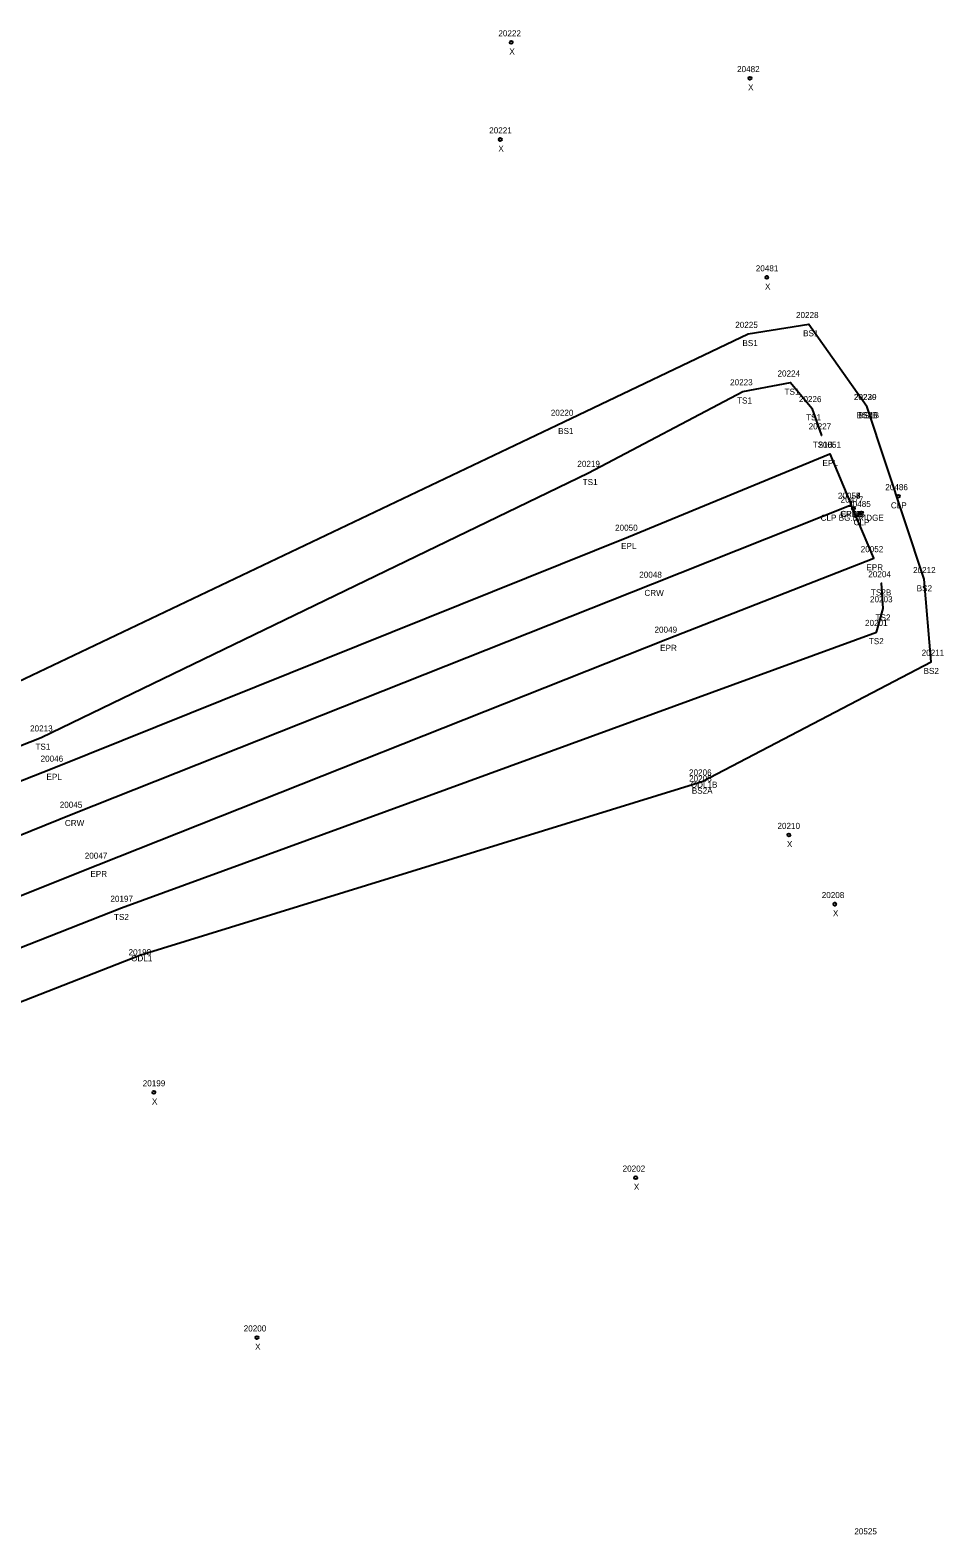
# Model space of a CAD drawing. Extents: x 1966740 to 1969291, y 1117378 to 1118461.
# Drawn here: x 1967562.8 to 1967713.2, y 1117652.7 to 1117901 of the extents above; entities that cross this region are included whole.
import ezdxf

# ---------------------------------------------------------------- set-up
doc = ezdxf.new("R2010")
doc.units = 0
for name, color, linetype in [('RD_DTM_BkLn1', 7, 'Continuous'), ('RD_DTM_BkLn2', 7, 'Continuous'), ('RD_EX_H2O', 7, 'Continuous'), ('RD_EX_H2O_txCode', 7, 'Continuous'), ('RD_EX_Road', 7, 'Continuous'), ('RD_EX_Road_txCode', 7, 'Continuous'), ('RD_SMD_Locator', 7, 'Continuous'), ('RD_SMD_Misc', 7, 'Continuous')]:
    doc.layers.add(name, color=color, linetype=linetype)

msp = doc.modelspace()

# ---------------------------------------------------------------- linework, layer by layer
at = {"layer": 'RD_DTM_BkLn1'}
msp.add_lwpolyline([(1966772.57, 1117449.88), (1966874.49, 1117489.87), (1966974.64, 1117529.93), (1967075.06, 1117571.68), (1967175.91, 1117613.34), (1967274.11, 1117653.69), (1967325.25, 1117674.8), (1967374.73, 1117695), (1967473.9, 1117733.1), (1967569.8, 1117771.9), (1967665.19, 1117809.79), (1967697.89, 1117822.8)], dxfattribs=at)
at = {"layer": 'RD_DTM_BkLn2'}
for points in [[(1967560.73, 1117793.63), (1967650.63, 1117836.46), (1967680.95, 1117850.94), (1967690.95, 1117852.56), (1967700.5, 1117839.06)], [(1966768.15, 1117461.43), (1966869.41, 1117499.34), (1967070.52, 1117582.35), (1967171.25, 1117624.02), (1967269.74, 1117664.9), (1967320.21, 1117685.71), (1967369.37, 1117708.48), (1967468.51, 1117746.66), (1967564.6, 1117784.47), (1967654.68, 1117828.05), (1967680.1, 1117841.48), (1967687.91, 1117842.93), (1967691.45, 1117838.71), (1967693.03, 1117834.22)], [(1967673.4, 1117777.22), (1967711.06, 1117796.94), (1967709.93, 1117810.55), (1967700.5, 1117839.06)], [(1967334.06, 1117655.75), (1967334.81, 1117659.44), (1967379.1, 1117675.46), (1967480.83, 1117718.27), (1967577.81, 1117756.42), (1967702.07, 1117801.85), (1967703.17, 1117805.75), (1967702.89, 1117809.87)]]:
    msp.add_lwpolyline(points, dxfattribs=at)
at = {"layer": 'RD_EX_H2O'}
msp.add_lwpolyline([(1967336.04, 1117656.91), (1967380.56, 1117671.84), (1967483.89, 1117710.7), (1967580.8, 1117748.62), (1967673.4, 1117777.22)], dxfattribs=at)
at = {"layer": 'RD_EX_Road'}
for points in [[(1966769.51, 1117457.48), (1966870.16, 1117497.34), (1966971.19, 1117538.95), (1967071.09, 1117580.24), (1967172.6, 1117621.53), (1967270.79, 1117661.66), (1967321.12, 1117682.57), (1967371.52, 1117702.88), (1967470.26, 1117741.55), (1967566.67, 1117779.5), (1967661.25, 1117817.53), (1967694.4, 1117831.19), (1967697.89, 1117822.8)], [(1967340.03, 1117669.86), (1967379.26, 1117686.2), (1967476.09, 1117724.39), (1967573.92, 1117763.51), (1967667.7, 1117800.74), (1967701.64, 1117814), (1967697.89, 1117822.8)]]:
    msp.add_lwpolyline(points, dxfattribs=at)
at = {"layer": 'RD_SMD_Locator'}
for centre, radius in [((1967641.96, 1117898.96), 0.25), ((1967681.25, 1117893.06), 0.25), ((1967640.16, 1117882.97), 0.25), ((1967684.04, 1117860.25), 0.25), ((1967680.95, 1117850.94), 0.001), ((1967690.95, 1117852.56), 0.001), ((1967680.1, 1117841.48), 0.001), ((1967687.91, 1117842.93), 0.001), ((1967691.45, 1117838.71), 0.001), ((1967700.5, 1117839.06), 0.001), ((1967700.5, 1117839.06), 0.001), ((1967650.63, 1117836.46), 0.001), ((1967693.03, 1117834.22), 0.001), ((1967694.4, 1117831.19), 0.001), ((1967654.68, 1117828.05), 0.001), ((1967705.67, 1117824.21), 0.25), ((1967697.89, 1117822.8), 0.001), ((1967697.89, 1117822.8), 0.001), ((1967697.89, 1117822.8), 0.001), ((1967698.29, 1117822.17), 0.25), ((1967699.54, 1117821.44), 0.25), ((1967661.25, 1117817.53), 0.001), ((1967701.64, 1117814), 0.001), ((1967665.19, 1117809.79), 0.001), ((1967702.89, 1117809.87), 0.001), ((1967709.93, 1117810.55), 0.001), ((1967703.17, 1117805.75), 0.001), ((1967702.07, 1117801.85), 0.001), ((1967667.7, 1117800.74), 0.001), ((1967711.06, 1117796.94), 0.001), ((1967564.6, 1117784.47), 0.001), ((1967566.67, 1117779.5), 0.001), ((1967673.4, 1117777.22), 0.001), ((1967673.4, 1117777.22), 0.001), ((1967569.8, 1117771.9), 0.001), ((1967687.66, 1117768.42), 0.25), ((1967573.92, 1117763.51), 0.001), ((1967695.23, 1117757.03), 0.25), ((1967577.81, 1117756.42), 0.001), ((1967580.8, 1117748.62), 0.001), ((1967583.14, 1117726.03), 0.25), ((1967662.45, 1117711.98), 0.25), ((1967600.11, 1117685.65), 0.25)]:
    msp.add_circle(centre, radius, dxfattribs=at)

# ---------------------------------------------------------------- texts
at = {"layer": 'RD_EX_H2O_txCode'}
for s, p in [('20205', (1967671.24, 1117777.22)), ('ODL1B', (1967671.51, 1117776.22)), ('20198', (1967578.97, 1117748.62)), ('ODL1', (1967579.39, 1117747.62))]:
    msp.add_text(s, height=1, dxfattribs=at).set_placement(p)
at = {"layer": 'RD_EX_Road_txCode'}
for s, p in [('20051', (1967692.52, 1117832.19)), ('EPL', (1967693.19, 1117829.19)), ('20054', (1967695.73, 1117823.8)), ('20055', (1967695.73, 1117823.8)), ('EPRB', (1967696.19, 1117820.8)), ('EPLB', (1967696.22, 1117820.8)), ('20050', (1967659.05, 1117818.53)), ('EPL', (1967660.04, 1117815.53)), ('20052', (1967699.48, 1117815)), ('EPR', (1967700.41, 1117812)), ('20049', (1967665.54, 1117801.74)), ('EPR', (1967666.47, 1117798.74)), ('20046', (1967564.49, 1117780.5)), ('EPL', (1967565.46, 1117777.5)), ('20047', (1967571.76, 1117764.51)), ('EPR', (1967572.69, 1117761.51))]:
    msp.add_text(s, height=1, dxfattribs=at).set_placement(p)
at = {"layer": 'RD_SMD_Misc'}
for s, p in [('20222', (1967639.84, 1117899.96)), ('X', (1967641.65, 1117896.96)), ('20482', (1967679.13, 1117894.06)), ('X', (1967680.94, 1117891.06)), ('20221', (1967638.33, 1117883.97)), ('X', (1967639.84, 1117880.97)), ('20481', (1967682.21, 1117861.25)), ('X', (1967683.73, 1117858.25)), ('20228', (1967688.83, 1117853.56)), ('20225', (1967678.83, 1117851.94)), ('BS1', (1967690, 1117850.56)), ('BS1', (1967680.01, 1117848.94)), ('20223', (1967677.98, 1117842.48)), ('20224', (1967685.79, 1117843.93)), ('TS1', (1967686.95, 1117840.93)), ('20230', (1967698.35, 1117840.06)), ('20229', (1967698.38, 1117840.06)), ('TS1', (1967679.14, 1117839.48)), ('20226', (1967689.31, 1117839.71)), ('20220', (1967648.47, 1117837.46)), ('TS1', (1967690.49, 1117836.71)), ('20227', (1967690.91, 1117835.22)), ('BS2B', (1967698.8, 1117837.06)), ('BS1B', (1967699.09, 1117837.06)), ('BS1', (1967649.68, 1117834.46)), ('TS1B', (1967691.6, 1117832.22)), ('20219', (1967652.84, 1117829.05)), ('TS1', (1967653.72, 1117826.05)), ('20486', (1967703.53, 1117825.21)), ('20053', (1967695.73, 1117823.8)), ('20477', (1967696.18, 1117823.17)), ('CLP BG.BRIDGE', (1967692.88, 1117820.17)), ('CRWB', (1967696.1, 1117820.8)), ('20485', (1967697.42, 1117822.44)), ('CLP', (1967704.45, 1117822.21)), ('CLP', (1967698.31, 1117819.44)), ('20048', (1967663.03, 1117810.79)), ('20204', (1967700.73, 1117810.87)), ('20212', (1967708.1, 1117811.55)), ('CRW', (1967663.88, 1117807.79)), ('TS2B', (1967701.17, 1117807.87)), ('BS2', (1967708.7, 1117808.55)), ('20203', (1967701.01, 1117806.75)), ('20201', (1967700.19, 1117802.85)), ('TS2', (1967701.93, 1117803.75)), ('TS2', (1967700.82, 1117799.85)), ('20211', (1967709.51, 1117797.94)), ('BS2', (1967709.83, 1117794.94)), ('20213', (1967562.76, 1117785.47)), ('TS1', (1967563.64, 1117782.47)), ('20206', (1967671.22, 1117778.22)), ('BS2A', (1967671.68, 1117775.22)), ('20045', (1967567.64, 1117772.9)), ('CRW', (1967568.49, 1117769.9)), ('20210', (1967685.78, 1117769.42)), ('X', (1967687.34, 1117766.42)), ('20197', (1967575.98, 1117757.42)), ('20208', (1967693.07, 1117758.03)), ('TS2', (1967576.57, 1117754.42)), ('X', (1967694.91, 1117755.03)), ('20199', (1967581.3, 1117727.03)), ('X', (1967582.82, 1117724.03)), ('20202', (1967660.29, 1117712.98)), ('X', (1967662.14, 1117709.98)), ('20200', (1967597.92, 1117686.65)), ('X', (1967599.8, 1117683.65)), ('20525', (1967698.43, 1117653.23))]:
    msp.add_text(s, height=1, dxfattribs=at).set_placement(p)

doc.saveas('drawing.dxf')
